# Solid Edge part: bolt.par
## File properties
Author: Deepak Maini
Template: Normal.par
Last saved by: MYPC
Revision: 3
Application: Solid Edge
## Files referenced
..\Asm.asm
<D:\sld-edg-15\cd-models\c09-sld-edg-15\figure9-8to10\Asm.asm
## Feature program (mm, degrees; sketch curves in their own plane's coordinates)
sketch for "unnamed Protrusion 1" plane through (0, 0, 0) normal (0, 0, 1) x-axis (1, 0, 0)
  circle centre (38.1, -42.8142) radius 3.175
extrude "unnamed Protrusion 1" add finite 25.4 along +normal
sketch for "unnamed Protrusion 2" plane through (38.1, -42.8142, 25.4) normal (0, 0, 1) x-axis (0, 1, 0)
  line (-3, 5.1962) -> (3, 5.1962)
  line (3, 5.1962) -> (6, 0)
  line (6, 0) -> (3, -5.1962)
  line (3, -5.1962) -> (-3, -5.1962)
  line (-3, -5.1962) -> (-6, 0)
  line (-6, 0) -> (-3, 5.1962)
extrude "unnamed Protrusion 2" add finite 3.5 along +normal
sketch for "unnamed RevolvedCutout 1" plane through (32.9038, -45.8142, 28.9) normal (0.5, -0.866025, 0) x-axis (0, 0, -1)
  line (0.9926, 12) -> (0, 10.9932)
revolve "unnamed RevolvedCutout 1" cut finite 360 deg about sketch line (0, 6) -> (9.5765, 6)
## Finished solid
Body 1: solid body, 11 faces, 21 edges, 12 vertices.
  Faces by surface: plane 9, cone 1, cylinder 1
  Edges by curve: line 12, intersection 6, circle 3
Bounding box of the edges (mm): 10.392 x 12.000 x 28.900, from (32.9038, -48.8142, 0) to (43.2962, -36.8142, 28.9).
Cylindrical faces by radius (mm): R3.175 x1
Conical faces (half-angle, radius in mm at the cone's reference point): 45.4057 deg R6 x1
Planar faces by outward normal: +x 1, +z 1, -x 1, -z 2, oblique 4
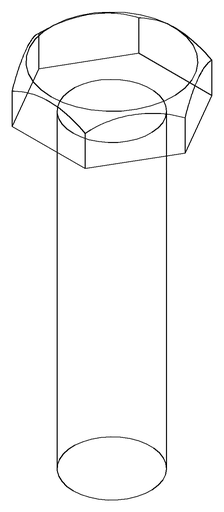
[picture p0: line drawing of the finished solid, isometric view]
